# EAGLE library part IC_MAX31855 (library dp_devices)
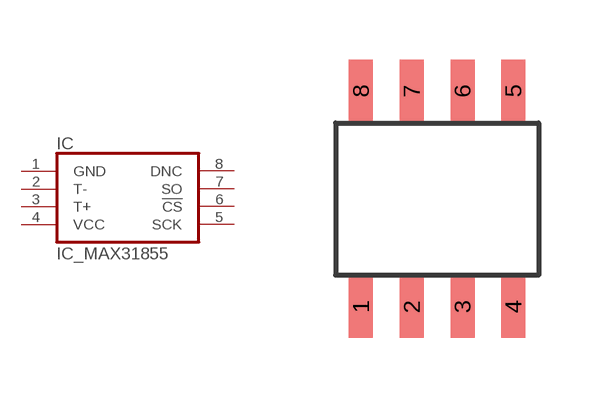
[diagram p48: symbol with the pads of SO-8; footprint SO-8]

Designator prefix IC

## IC_MAX31855-SO-8  [SO-8]
1  GND  pwr
2  T-  in
3  T+  in
4  VCC  pwr
5  SCK  in
6  !CS  in
7  SO  out
8  DNC  nc

## Footprint SO-8 (pad centres in mm)
smd 0.6 x 1.55: 1 -1.905,-2.69; 2 -0.635,-2.69; 3 0.635,-2.69; 4 1.905,-2.69; 5 1.905,2.71; 6 0.635,2.71; 7 -0.635,2.71; 8 -1.905,2.71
